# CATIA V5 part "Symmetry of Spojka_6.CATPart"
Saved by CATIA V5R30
Part number: Symmetry of Spojka_6
Bounding box of the stored display mesh (mm): x -8.66 to 8.66, y -7.5 to 7.5, z -9 to 17
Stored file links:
  E:\Bakalarka\Model\Forma_v7\Symmetry of Spojka_6.CATPart
  E:\Bakalarka\Model\Forma_v7\Spojka_1.CATPart
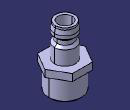
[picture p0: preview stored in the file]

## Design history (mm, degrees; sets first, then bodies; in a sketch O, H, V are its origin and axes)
Body1 (main body)
  Body2 "Body from original PartBody"
    Solid1: linked copy from another document
  Assemble1: tool Body2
